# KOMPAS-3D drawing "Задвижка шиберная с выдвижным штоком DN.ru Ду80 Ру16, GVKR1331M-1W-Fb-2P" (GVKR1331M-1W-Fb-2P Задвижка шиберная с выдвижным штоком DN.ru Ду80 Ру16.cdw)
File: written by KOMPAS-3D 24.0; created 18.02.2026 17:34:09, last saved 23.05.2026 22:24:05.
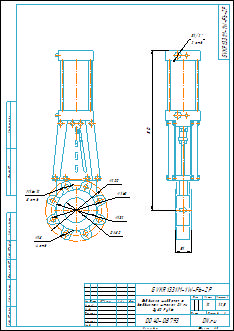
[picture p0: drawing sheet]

Document properties: Автор: R2D2; Форматы листов документа: A3; Полное имя файла: GVKR1331M-1W-Fb-2P Задвижка шиберная с выдвижным штоком DN.ru Ду80 Ру16.m3d; Масса: 12; Наименование: Задвижка шиберная с выдвижным штоком DN.ru Ду80 Ру16; Количество листов документа: 1; Примечание: D040-08793

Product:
- Part/product: Задвижка шиберная с выдвижным штоком DN.ru Ду80 Ру16  | designation GVKR1331M-1W-Fb-2P
    Масса: 12
    Раздел спецификации: Прочие изделия
    Примечание: D040-08793

Views: Вид 1, Спереди, Проекционный вид 2
Referenced files in E:\Работа\Зайцев\GVKR1331N-2W-Fb-S Задвижка шиберная с выдвижным штоком DN.ru Ду50-300 Ру10\DN50\: GVKR1331N-2W-Fb-S Задвижка шиберная DN.ru Ду50 Ру10.m3d
Referenced files in E:\Работа\Зайцев\GVKR1331M-1W-Fb-2P Задвижка шиберная с выдвижным штоком DN.ru Ду50-300 Ру16-10-6 с пневмоприводом\исходные материалы\DN80\DN80\: GVKR1331M-1W-Fb-2P Задвижка шиберная с выдвижным штоком DN.ru Ду80 Ру16.m3d
Referenced files in E:\Работа\Зайцев\Для компаса\: чертеж DN.ru А3.cdt
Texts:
  GVKR1331M-1W-Fb-2P
  чертеж DN.ru А3.cdt
  Задвижка шиберная с
  выдвижным штоком DN.ru
  Ду80 Ру16
  Задвижка шиберная с выдвижным штоком DN.ru Ду80 Ру16
  GVKR1331M-1W-Fb-2P Задвижка шиберная с выдвижным штоком DN.ru Ду80 Ру16
Dimensions and other numbers on the sheet: 0; 3; 2; 4; 16; 8 отв.; 18; 4 отв.; 200; 160; 132; 80; 2 отв.; 51; 510; 1:2,5; 1; 12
